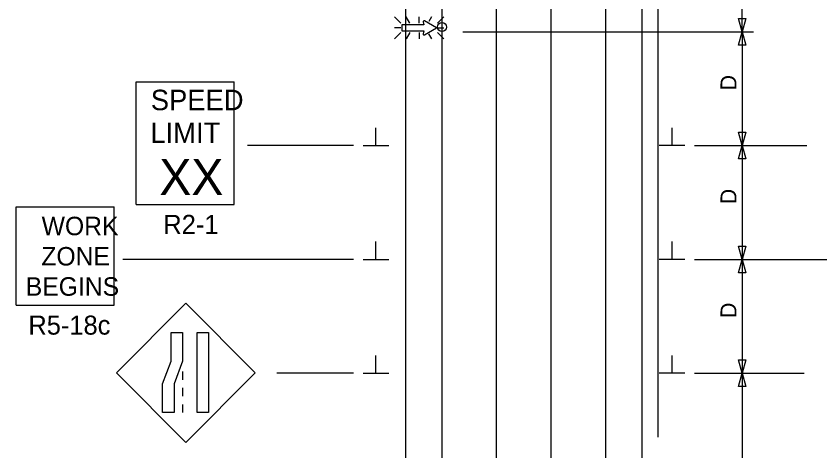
# Model space of a CAD drawing. Extents: x 16731 to 18475, y 7005 to 8303.
# Drawn here: x 16742 to 17095.5, y 7479.3 to 7670.3 of the extents above; entities that cross this region are included whole.
import ezdxf

# ---------------------------------------------------------------- set-up
doc = ezdxf.new("R2010")
doc.units = 0
for name, color, linetype in [('ALI_LEGAL_EX', 7, 'Continuous'), ('PAVT_EDGE_EX', 7, 'Continuous'), ('TRAFFIC_SIGNS_PR', 7, 'Continuous'), ('TYPICAL_TEXT_DIMEN_PR', 7, 'Continuous')]:
    doc.layers.add(name, color=color, linetype=linetype)

msp = doc.modelspace()

# ---------------------------------------------------------------- linework, layer by layer
at = {"layer": 'ALI_LEGAL_EX'}
for p, q in [((17024.17, 8303.41), (17024.17, 7485.27)), ((16953.23, 7307.34), (16953.23, 7890.11)), ((16977.23, 7389.77), (16977.23, 7890.11)), ((16977.23, 7307.34), (16977.23, 7890.11)), ((16977.23, 7307.34), (16977.23, 7890.11))]:
    msp.add_line(p, q, dxfattribs=at)
for points in [[(16953.23, 7579.92), (16953.23, 7604.92)], [(16977.23, 7579.92), (16977.23, 7604.92)], [(16953.23, 7479.92), (16953.23, 7504.92)], [(16977.23, 7479.92), (16977.23, 7504.92)]]:
    msp.add_lwpolyline(points, dxfattribs=at)
at = {"layer": 'PAVT_EDGE_EX'}
for p, q in [((16913.23, 7890.11), (16913.23, 7307.34)), ((16929.23, 7890.11), (16929.23, 7307.34)), ((17001.23, 7890.11), (17001.23, 7307.34)), ((17017.23, 7890.11), (17017.23, 7307.34))]:
    msp.add_line(p, q, dxfattribs=at)
at = {"layer": 'TRAFFIC_SIGNS_PR'}
for p, q in [((16911.14, 7667.15), (16908.32, 7669.97)), ((16913.43, 7669.97), (16915.06, 7667.15)), ((16919.22, 7667.15), (16919.22, 7669.97)), ((16924.69, 7669.97), (16923.48, 7667.88)), ((16930.13, 7669.97), (16927.31, 7667.15)), ((16911.14, 7665.12), (16908.32, 7665.12)), ((16927.31, 7665.12), (16930.13, 7665.12)), ((16911.14, 7663.09), (16908.32, 7660.27)), ((16915.09, 7663.09), (16913.46, 7660.27)), ((16919.22, 7663.09), (16919.22, 7660.27)), ((16923.4, 7662.45), (16924.67, 7660.27)), ((16930.13, 7660.27), (16927.31, 7663.09)), ((16794.71, 7641.48), (16837.91, 7641.48)), ((16794.71, 7587.48), (16794.71, 7641.48)), ((16837.91, 7587.48), (16837.91, 7641.48)), ((16794.71, 7587.48), (16837.91, 7587.48)), ((16741.95, 7543.24), (16741.95, 7586.44)), ((16741.95, 7586.44), (16785.15, 7586.44)), ((16785.15, 7543.24), (16785.15, 7586.44)), ((16741.95, 7543.24), (16785.15, 7543.24)), ((16816.61, 7544.14), (16786.06, 7513.59)), ((16847.15, 7513.59), (16816.61, 7544.14)), ((16786.06, 7513.59), (16816.61, 7483.04)), ((16815.2, 7514.14), (16815.2, 7510.54)), ((16816.61, 7483.04), (16847.15, 7513.59)), ((16815.2, 7506.94), (16815.2, 7503.34)), ((16815.2, 7499.74), (16815.2, 7496.14))]:
    msp.add_line(p, q, dxfattribs=at)
for points in [[(16921.05, 7667.8), (16921.28, 7666.51), (16911.56, 7666.51), (16911.56, 7663.76), (16921.28, 7663.76), (16921.05, 7662.46)], [(16921.55, 7662.11), (16926.86, 7665.12), (16921.55, 7668.16)]]:
    msp.add_lwpolyline(points, dxfattribs=at)
for points in [[(16815.2, 7531.29), (16815.2, 7518.72), (16811.44, 7508.72), (16811.44, 7496.14), (16806.39, 7496.14), (16806.39, 7508.72), (16810.15, 7518.72), (16810.15, 7531.29)], [(16826.61, 7531.29), (16826.61, 7496.14), (16821.55, 7496.14), (16821.55, 7531.29)]]:
    msp.add_lwpolyline(points, close=True, dxfattribs=at)
msp.add_circle((16929.24, 7665.49), 2, dxfattribs=at)
for centre, start, end in [((16921.38, 7667.86), 61.4833, 189.9593), ((16921.38, 7662.4), 170.7308, 298.8916)]:
    msp.add_arc(centre, 0.341, start, end, dxfattribs=at)
at = {"layer": 'TYPICAL_TEXT_DIMEN_PR'}
for p, q in [((17061.33, 7663.44), (17061.33, 7694)), ((17061.33, 7663.44), (17059.76, 7669.3)), ((17059.76, 7669.3), (17061.33, 7669.3)), ((17061.33, 7669.3), (17062.9, 7669.3)), ((17062.9, 7669.3), (17061.33, 7663.44)), ((16938.49, 7663.44), (17066.33, 7663.44)), ((17059.76, 7657.58), (17061.33, 7663.44)), ((17061.33, 7663.44), (17061.33, 7613.44)), ((17061.33, 7663.44), (17062.9, 7657.58)), ((17061.33, 7657.58), (17059.76, 7657.58)), ((17062.9, 7657.58), (17061.33, 7657.58)), ((16900.21, 7613.44), (16900.21, 7621.22)), ((17030.46, 7613.44), (17030.46, 7621.22)), ((17061.33, 7613.44), (17059.76, 7619.3)), ((17059.76, 7619.3), (17061.33, 7619.3)), ((17061.33, 7619.3), (17062.9, 7619.3)), ((17062.9, 7619.3), (17061.33, 7613.44)), ((16890.33, 7613.44), (16843.78, 7613.44)), ((16894.58, 7613.44), (16905.83, 7613.44)), ((17036.08, 7613.44), (17024.83, 7613.44)), ((17040.33, 7613.44), (17089.68, 7613.44)), ((17059.76, 7607.58), (17061.33, 7613.44)), ((17061.33, 7613.44), (17062.9, 7607.58)), ((17061.33, 7613.44), (17061.33, 7563.44)), ((17061.33, 7607.58), (17059.76, 7607.58)), ((17062.9, 7607.58), (17061.33, 7607.58)), ((16900.21, 7563.44), (16900.21, 7571.22)), ((17030.46, 7563.44), (17030.46, 7571.22)), ((17061.33, 7563.44), (17059.76, 7569.3)), ((17059.76, 7569.3), (17061.33, 7569.3)), ((17061.33, 7569.3), (17062.9, 7569.3)), ((17062.9, 7569.3), (17061.33, 7563.44)), ((16890.33, 7563.44), (16788.84, 7563.44)), ((16894.58, 7563.44), (16905.83, 7563.44)), ((17036.08, 7563.44), (17024.83, 7563.44)), ((17040.33, 7563.44), (17167.53, 7563.44)), ((17059.76, 7557.58), (17061.33, 7563.44)), ((17061.33, 7563.44), (17062.9, 7557.58)), ((17061.33, 7563.44), (17061.33, 7513.44)), ((17061.33, 7557.58), (17059.76, 7557.58)), ((17062.9, 7557.58), (17061.33, 7557.58)), ((16900.21, 7513.44), (16900.21, 7521.22)), ((17030.46, 7513.44), (17030.46, 7521.22)), ((17061.33, 7513.44), (17059.76, 7519.3)), ((17059.76, 7519.3), (17061.33, 7519.3)), ((17061.33, 7519.3), (17062.9, 7519.3)), ((17062.9, 7519.3), (17061.33, 7513.44)), ((16890.33, 7513.44), (16856.62, 7513.44)), ((16894.58, 7513.44), (16905.83, 7513.44)), ((17036.08, 7513.44), (17024.83, 7513.44)), ((17040.33, 7513.44), (17088.54, 7513.44)), ((17059.76, 7507.58), (17061.33, 7513.44)), ((17061.33, 7513.44), (17061.33, 7413.44)), ((17061.33, 7513.44), (17062.9, 7507.58)), ((17061.33, 7507.58), (17059.76, 7507.58)), ((17062.9, 7507.58), (17061.33, 7507.58))]:
    msp.add_line(p, q, dxfattribs=at)

# ---------------------------------------------------------------- texts
at = {"layer": 'TRAFFIC_SIGNS_PR'}
for s, height, p in [('SPEED', 9, (16801.2, 7628.95)), ('LIMIT', 9, (16801.02, 7614.55)), ('XX', 15.785, (16804.96, 7591.7)), ('WORK', 8.119, (16753.2, 7574.03)), ('R2-1', 8.37, (16806.72, 7574.61)), ('ZONE', 8.119, (16753.07, 7560.74)), ('BEGINS', 8.119, (16746.23, 7547.46)), ('R5-18c', 8.37, (16747.36, 7530.37))]:
    msp.add_text(s, height=height, dxfattribs=at).set_placement(p)
at = {"layer": 'TYPICAL_TEXT_DIMEN_PR'}
for p in [(17058.77, 7637.66), (17058.77, 7587.66), (17058.77, 7537.66)]:
    msp.add_text('D', height=7, rotation=90, dxfattribs=at).set_placement(p)

doc.saveas('drawing.dxf')
